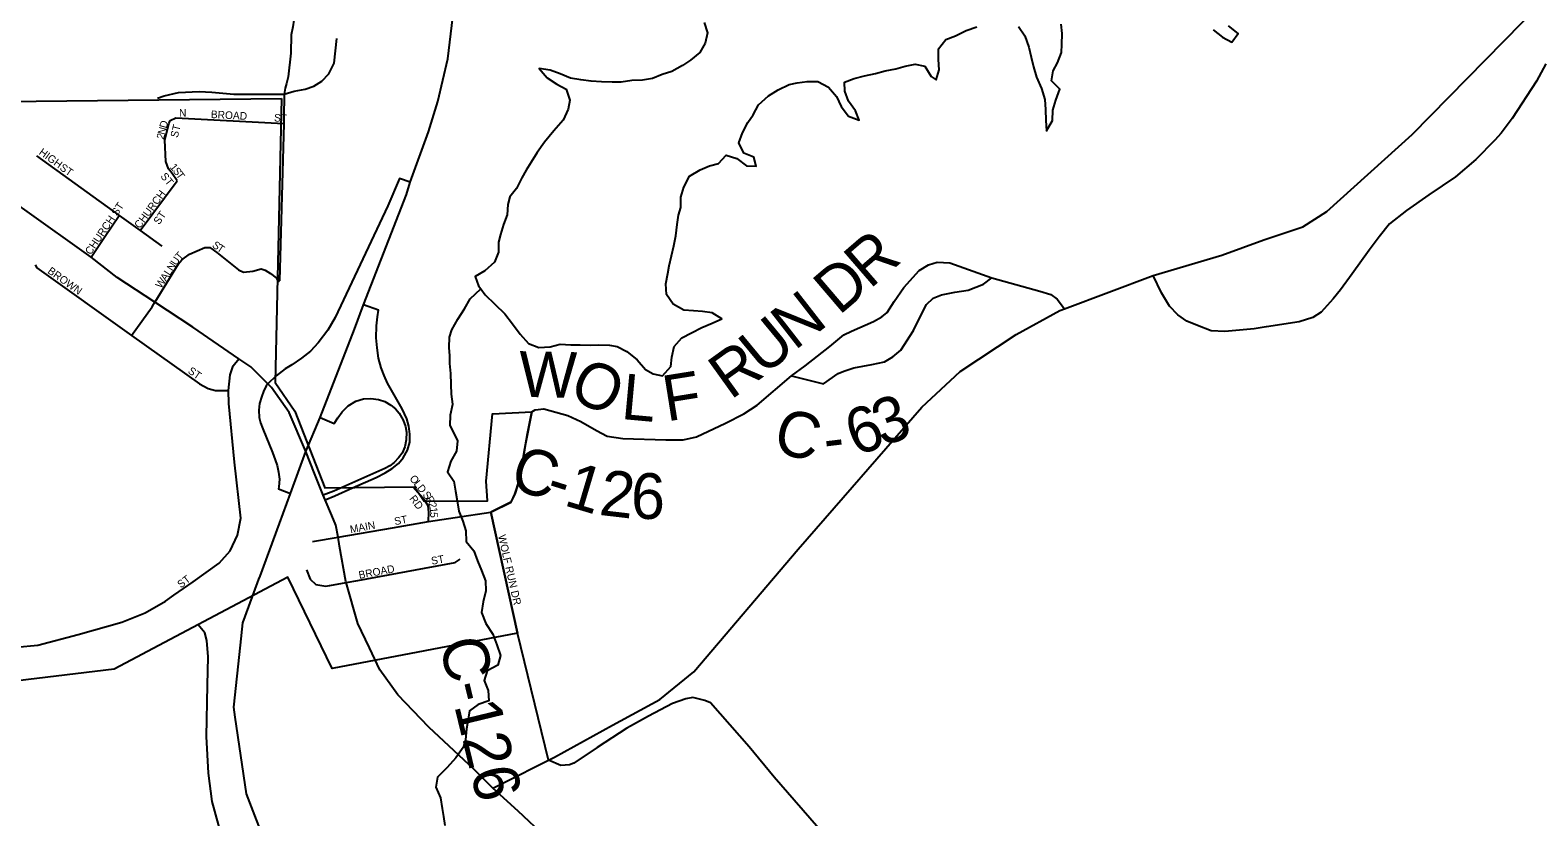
# Model space of a CAD drawing. Extents: x -22 to 431, y -18 to 160.
# Drawn here: x 323.412 to 325.283, y 148.89 to 149.867 of the extents above; entities that cross this region are included whole.
import ezdxf

# ---------------------------------------------------------------- set-up
doc = ezdxf.new("R2010")
doc.units = 0
for name, color, linetype in [('GM_X_Adjacent_County_Text', 7, 'Continuous'), ('GM_X_City_Street', 7, 'Continuous'), ('GM_X_Corporation_Text', 7, 'Continuous'), ('GM_X_County_ROW', 7, 'Continuous'), ('GM_X_County_Subdivision_Text', 7, 'Continuous'), ('GM_X_Minor_River_Text', 7, 'Continuous'), ('GM_X_Rail_Line', 7, 'Continuous'), ('GM_X_Section_Text', 7, 'Continuous'), ('GM_X_State_Route', 7, 'Continuous'), ('GM_X_Township_Subdivision', 7, 'Continuous'), ('GM_X_Township_Subdivision_Text', 7, 'Continuous')]:
    doc.layers.add(name, color=color, linetype=linetype)

msp = doc.modelspace()

# ---------------------------------------------------------------- linework, layer by layer
at = {"layer": 'GM_X_Adjacent_County_Text'}
for points in [[(324.3569, 149.4379), (324.3569, 149.4379), (324.3735, 149.4501), (324.4045, 149.474), (324.4219, 149.4885), (324.4314, 149.4934), (324.4587, 149.5052), (324.4689, 149.5109), (324.4753, 149.5166), (324.484, 149.5303), (324.4961, 149.5477), (324.5154, 149.5686), (324.5268, 149.5758), (324.5374, 149.5789), (324.5533, 149.5782), (324.6054, 149.5594)], [(324.3569, 149.4379), (324.3966, 149.4277), (324.4148, 149.4407), (324.4216, 149.4437), (324.4341, 149.4479), (324.4564, 149.4517), (324.472, 149.4552), (324.4826, 149.4612), (324.4924, 149.4697), (324.5083, 149.4939), (324.5219, 149.522), (324.5245, 149.5265), (324.5325, 149.5341), (324.5431, 149.5383), (324.5594, 149.5418), (324.576, 149.5441), (324.5949, 149.5517), (324.6054, 149.5594)], [(324.6054, 149.5594), (324.665, 149.543), (324.6786, 149.5389), (324.6866, 149.5328), (324.6954, 149.521)], [(324.0343, 149.3931), (324.0343, 149.3931), (324.0384, 149.3954), (324.0494, 149.3969), (324.0793, 149.3886), (324.0952, 149.381), (324.1146, 149.3697), (324.1278, 149.3629), (324.1475, 149.3599), (324.2009, 149.3581), (324.2221, 149.3581), (324.2388, 149.3619), (324.2747, 149.379), (324.2974, 149.3904), (324.3141, 149.4015), (324.3569, 149.4379)], [(324.0551, 148.9604), (324.0166, 149.1182)], [(324.396, 148.8691), (324.3353, 148.9392), (324.3042, 148.9767), (324.2561, 149.0316), (324.2493, 149.0346), (324.2341, 149.038), (324.2254, 149.0365), (324.2091, 149.0308), (324.1792, 149.0148), (324.1571, 149.0026)], [(324.1571, 149.0026), (324.1567, 149.0024), (324.1524, 149), (324.1156, 148.976), (324.0865, 148.9566), (324.0812, 148.9544), (324.0706, 148.9536), (324.0551, 148.9604)]]:
    msp.add_lwpolyline(points, dxfattribs=at)
at = {"layer": 'GM_X_County_ROW'}
for points in [[(323.9862, 148.9254), (323.9991, 148.9322), (324.0551, 148.9604), (324.0626, 148.9642), (324.1346, 149.0037), (324.1932, 149.0357), (324.2356, 149.0699), (324.3652, 149.2224), (324.5186, 149.3989), (324.5663, 149.4432), (324.6355, 149.4891), (324.69, 149.5189), (324.6954, 149.521), (324.8058, 149.5625), (324.8909, 149.5875), (324.9432, 149.6067), (324.9913, 149.6229), (325.0212, 149.642), (325.1271, 149.7375), (325.2643, 149.8771), (325.4249, 150.0397)], [(323.6708, 149.4589), (323.6136, 149.4982), (323.5665, 149.5292), (323.5196, 149.56), (323.4874, 149.5853), (323.4053, 149.644), (323.398, 149.6488)], [(323.7648, 149.3166), (323.7541, 149.3438), (323.7332, 149.3923), (323.7112, 149.4233), (323.7069, 149.4277), (323.6984, 149.4361), (323.6855, 149.4488), (323.6708, 149.4589)], [(323.7958, 149.226), (323.7939, 149.2374), (323.7913, 149.2524), (323.7862, 149.2644), (323.7779, 149.2839), (323.7756, 149.2895), (323.7648, 149.3166)], [(323.8329, 149.0997), (323.8232, 149.1206), (323.8186, 149.1303), (323.8038, 149.1809), (323.8034, 149.1821), (323.7958, 149.226)], [(323.9862, 148.9254), (323.9627, 148.9489), (323.9066, 149.0015), (323.8679, 149.0413), (323.8456, 149.0727), (323.8329, 149.0997)], [(324.3568, 148.2215), (324.3548, 148.2346), (324.3377, 148.3191), (324.3221, 148.3825), (324.2979, 148.4291), (324.2767, 148.4535), (324.2271, 148.5231), (324.1871, 148.5703), (324.1592, 148.6143), (324.1333, 148.6627), (324.1231, 148.6939), (324.1142, 148.7241), (324.1109, 148.7352), (324.1033, 148.7682), (324.0965, 148.7845), (324.0718, 148.8338), (324.0517, 148.8648), (324.0173, 148.897), (323.9862, 148.9254)]]:
    msp.add_lwpolyline(points, dxfattribs=at)
at = {"layer": 'GM_X_County_Subdivision_Text'}
msp.add_lwpolyline([(323.7239, 149.7823), (323.7157, 149.4296), (323.7403, 149.3939), (323.7774, 149.2986), (323.8886, 149.2997), (323.9008, 149.282), (323.9793, 149.2826), (323.9779, 149.3069), (323.9858, 149.3904), (324.0343, 149.3931), (324.0262, 149.3511), (324.0202, 149.3127), (324.0133, 149.2907), (324.0085, 149.2807), (323.9836, 149.2684), (324.0166, 149.1182), (323.7864, 149.074), (323.7314, 149.1875), (323.5161, 149.0733), (323.3959, 149.0588), (323.3327, 149.089), (323.2169, 149.0915), (323.2286, 149.7771)], close=True, dxfattribs=at)
at = {"layer": 'GM_X_Minor_River_Text'}
for points in [[(323.7392, 149.8797), (323.7377, 149.8713), (323.7358, 149.8615), (323.7351, 149.8387), (323.7321, 149.8091), (323.7298, 149.8008), (323.7284, 149.7951), (323.7272, 149.7875), (323.7268, 149.7583), (323.7266, 149.7514), (323.7213, 149.5557)], [(323.7272, 149.7875), (323.7395, 149.7914), (323.7531, 149.7938), (323.7637, 149.7976), (323.7738, 149.8038), (323.7825, 149.813), (323.7892, 149.8263), (323.7924, 149.8567)], [(325.2932, 149.8252), (325.2816, 149.8039), (325.2512, 149.7573), (325.2377, 149.7394), (325.2298, 149.7306), (325.2062, 149.7065), (325.181, 149.6851), (325.1478, 149.6628), (325.1203, 149.6433), (325.0992, 149.6264), (325.0861, 149.6104), (325.0737, 149.594), (325.0527, 149.5646), (325.0381, 149.5448), (325.0291, 149.5333), (325.014, 149.5169), (325.0039, 149.5104), (324.9869, 149.5049), (324.9464, 149.4986)], [(323.5697, 149.7827), (323.578, 149.7854), (323.5958, 149.7896), (323.6215, 149.7911), (323.6371, 149.79), (323.6647, 149.7878), (323.7272, 149.7875)], [(324.9464, 149.4986), (324.9461, 149.4985), (324.9309, 149.4962), (324.8946, 149.4928), (324.8775, 149.4935), (324.8608, 149.5002), (324.8475, 149.5057), (324.8361, 149.5136), (324.8258, 149.5242), (324.8162, 149.5408), (324.8058, 149.5625)], [(323.856, 148.5271), (323.856, 148.5274), (323.8375, 148.5686), (323.8264, 148.5894), (323.8118, 148.6139), (323.7908, 148.6429), (323.7614, 148.6806), (323.7071, 148.7477), (323.696, 148.7639), (323.6792, 148.7957), (323.6499, 148.8637), (323.6378, 148.9088), (323.633, 148.944), (323.6305, 148.9899), (323.6319, 149.0536), (323.6328, 149.0885), (323.6311, 149.109), (323.6284, 149.1184), (323.6204, 149.1286)]]:
    msp.add_lwpolyline(points, dxfattribs=at)
at = {"layer": 'GM_X_Rail_Line'}
for points in [[(323.7541, 149.3438), (323.7718, 149.3859), (323.8142, 149.4956), (323.8253, 149.5261), (323.8788, 149.6629), (323.8836, 149.6785), (323.906, 149.7408), (323.9176, 149.7784), (323.9303, 149.8316), (323.9399, 149.9149), (323.9389, 150.0683), (323.9274, 150.2851), (323.911, 150.5141), (323.8962, 150.7806), (323.8747, 151.1376), (323.8507, 151.5599)], [(323.7445, 149.3178), (323.7541, 149.3438)], [(323.7212, 149.2544), (323.735, 149.2918), (323.7445, 149.3178)], [(323.6971, 149.1888), (323.7212, 149.2544)], [(323.6833, 149.1514), (323.6957, 149.1851), (323.6971, 149.1888)], [(323.6727, 149.103), (323.6757, 149.1309), (323.6833, 149.1514)], [(323.6662, 149.0139), (323.6644, 149.0261), (323.6727, 149.103)], [(324.2676, 147.6799), (324.2465, 147.7384), (324.2135, 147.824), (324.1675, 147.9385), (324.1073, 148.0954), (324.0457, 148.2492), (324.0077, 148.347), (323.9615, 148.4417), (323.9126, 148.5147), (323.8297, 148.6521), (323.766, 148.738), (323.706, 148.852), (323.6803, 148.9187), (323.6662, 149.0139)]]:
    msp.add_lwpolyline(points, dxfattribs=at)
at = {"layer": 'GM_X_Section_Text'}
for points in [[(323.5835, 149.6949), (323.5803, 149.7039), (323.5789, 149.7305), (323.5839, 149.751), (323.5857, 149.7548)], [(323.5857, 149.7548), (323.5925, 149.7583), (323.7266, 149.7514)], [(323.4198, 149.7109), (323.5224, 149.6369), (323.5484, 149.6182), (323.5753, 149.5988)], [(323.5484, 149.6182), (323.5943, 149.6799)], [(323.5943, 149.6799), (323.5881, 149.6893), (323.5835, 149.6949)], [(323.5049, 149.6111), (323.5224, 149.6369)], [(323.4874, 149.5853), (323.5049, 149.6111), (323.5049, 149.6111)], [(323.5668, 149.5297), (323.596, 149.5767), (323.6001, 149.5817), (323.6094, 149.5887), (323.6286, 149.5973), (323.6347, 149.5973), (323.6359, 149.5965)], [(323.6359, 149.5965), (323.636, 149.5964), (323.6435, 149.591), (323.6703, 149.5694), (323.6764, 149.5664), (323.6881, 149.5677), (323.6986, 149.5705), (323.7036, 149.5691), (323.7101, 149.565), (323.7169, 149.5594), (323.7193, 149.5553), (323.7205, 149.555), (323.7213, 149.5557)], [(323.4181, 149.5755), (323.42, 149.5721), (323.5376, 149.4878), (323.6221, 149.4277), (323.6328, 149.4221), (323.6419, 149.4196), (323.6579, 149.4194)], [(323.5376, 149.4878), (323.563, 149.5236), (323.5665, 149.5292), (323.5666, 149.5294), (323.5668, 149.5297)], [(323.3945, 149.1005), (323.4214, 149.1032), (323.4714, 149.1165), (323.5255, 149.1318), (323.5543, 149.1432), (323.5797, 149.1577), (323.5899, 149.1653), (323.6141, 149.182), (323.6463, 149.2052), (323.6599, 149.2204), (323.669, 149.2397), (323.6731, 149.261), (323.6655, 149.3304), (323.6582, 149.4035), (323.6579, 149.4194), (323.6601, 149.4392), (323.6639, 149.4502), (323.6708, 149.4589)], [(323.9836, 149.2684), (324.0086, 149.2809), (324.0134, 149.2908), (324.0154, 149.2971), (324.0203, 149.3132), (324.0246, 149.3405), (324.0291, 149.3663), (324.0343, 149.3931)], [(323.9063, 149.2567), (323.9065, 149.2684), (323.9057, 149.2763), (323.9018, 149.2827), (323.8876, 149.2992)], [(323.9392, 149.2617), (323.9836, 149.2684)], [(324.0166, 149.1182), (323.9836, 149.2684)], [(323.762, 149.232), (323.7939, 149.2374), (323.8616, 149.2491)], [(323.8616, 149.2491), (323.9063, 149.2567), (323.9392, 149.2617)], [(323.7833, 149.1773), (323.7835, 149.1773), (323.8038, 149.1809), (323.8183, 149.1834), (323.9391, 149.2059), (323.9455, 149.2101)], [(323.7549, 149.1966), (323.7592, 149.1853), (323.7665, 149.1786), (323.7786, 149.1764), (323.7833, 149.1773)]]:
    msp.add_lwpolyline(points, dxfattribs=at)
at = {"layer": 'GM_X_State_Route'}
for points in [[(323.8836, 149.6785), (323.87, 149.6827), (323.8555, 149.6488), (323.7904, 149.5102), (323.7811, 149.4943), (323.7694, 149.4788), (323.7597, 149.4682), (323.7486, 149.4597), (323.7367, 149.4514), (323.7281, 149.4466), (323.717, 149.4379), (323.7069, 149.4277)], [(323.7779, 149.2839), (323.7898, 149.2889), (323.8117, 149.2988), (323.8414, 149.3116), (323.8523, 149.3171), (323.8612, 149.3226), (323.8691, 149.329), (323.8747, 149.336), (323.8799, 149.3453), (323.8829, 149.3555), (323.8829, 149.3653), (323.8819, 149.3752), (323.8793, 149.3842), (323.8733, 149.3966), (323.8554, 149.4288), (323.8511, 149.4382), (323.8474, 149.4479), (323.8443, 149.4597), (323.8424, 149.4725), (323.8412, 149.4851), (323.8415, 149.4997), (323.8429, 149.511), (323.8443, 149.5192), (323.8253, 149.5261)], [(323.7069, 149.4277), (323.7045, 149.4253), (323.7014, 149.4184), (323.6992, 149.4123), (323.6965, 149.4034), (323.6954, 149.3953), (323.6959, 149.3861), (323.6976, 149.3793), (323.7004, 149.3718), (323.7126, 149.3424), (323.7159, 149.3336), (323.7183, 149.3265), (323.7201, 149.3181), (323.7211, 149.3093), (323.7205, 149.2997), (323.7199, 149.2974), (323.735, 149.2918)], [(323.7718, 149.3859), (323.7891, 149.3787), (323.7935, 149.3857), (323.7991, 149.393), (323.8064, 149.4004), (323.8159, 149.4062), (323.8253, 149.4092), (323.8345, 149.4097), (323.8441, 149.4085), (323.852, 149.4057), (323.8596, 149.4014), (323.8653, 149.3969), (323.8698, 149.3912), (323.8749, 149.3828), (323.8775, 149.375), (323.8787, 149.3676), (323.8786, 149.3582), (323.8766, 149.3497), (323.8734, 149.3417), (323.869, 149.3357), (323.8635, 149.3301), (323.858, 149.3261), (323.8518, 149.3226), (323.7885, 149.2945), (323.7756, 149.2895)]]:
    msp.add_lwpolyline(points, dxfattribs=at)
at = {"layer": 'GM_X_Township_Subdivision'}
for points in [[(324.2483, 149.8765), (324.2526, 149.8637), (324.2497, 149.8512), (324.243, 149.8393), (324.2313, 149.8297), (324.2215, 149.8232), (324.208, 149.8158), (324.1963, 149.8119), (324.1842, 149.8072), (324.1717, 149.8052), (324.1585, 149.8047), (324.1453, 149.8026), (324.1343, 149.8025), (324.121, 149.8031), (324.1081, 149.8037), (324.0952, 149.8055), (324.0823, 149.8076), (324.0694, 149.8128), (324.0573, 149.8176), (324.0436, 149.8197), (324.0536, 149.8081), (324.0654, 149.8002), (324.0772, 149.7939), (324.0815, 149.7803), (324.0797, 149.7689), (324.0734, 149.7552), (324.0618, 149.7422), (324.0502, 149.728), (324.0409, 149.7154), (324.0338, 149.7032), (324.0275, 149.6933), (324.0219, 149.6837), (324.0152, 149.6704), (324.007, 149.6601), (324.0048, 149.6506), (324.0038, 149.6377), (323.9994, 149.6259), (323.9954, 149.6133), (323.9932, 149.6038), (323.9929, 149.5913), (323.9881, 149.5791), (323.9761, 149.568), (323.9641, 149.561), (323.9684, 149.5497), (323.9711, 149.5458)], [(324.5299, 149.8095), (324.5364, 149.8054), (324.5401, 149.8179), (324.5392, 149.8308), (324.539, 149.8441), (324.5484, 149.8555), (324.5604, 149.8602), (324.5736, 149.8668), (324.5868, 149.8711)], [(324.6383, 149.8717), (324.6464, 149.86), (324.6515, 149.846), (324.6543, 149.8336), (324.657, 149.8218), (324.6609, 149.8086), (324.6671, 149.7946), (324.6711, 149.781), (324.672, 149.7685), (324.6725, 149.7549), (324.6734, 149.742), (324.6808, 149.755), (324.6811, 149.7679), (324.6847, 149.78), (324.6899, 149.7937), (324.6795, 149.8043), (324.6817, 149.8168), (324.6869, 149.8267), (324.6917, 149.8396), (324.6923, 149.8495), (324.6929, 149.8632), (324.6913, 149.8745)], [(324.88, 149.8675), (324.8918, 149.8585), (324.9032, 149.8522), (324.9111, 149.8629), (324.8992, 149.8726)], [(324.2098, 149.5269), (324.2014, 149.5386), (324.2008, 149.5522), (324.2034, 149.5648), (324.2048, 149.5743), (324.2106, 149.5994), (324.2131, 149.6115), (324.2149, 149.6256), (324.2166, 149.6373), (324.2192, 149.6468), (324.2194, 149.6597), (324.2231, 149.6723), (324.2301, 149.6856), (324.2433, 149.6937), (324.255, 149.6988), (324.266, 149.7016), (324.2757, 149.7119), (324.289, 149.7079), (324.3008, 149.6985), (324.3129, 149.6983), (324.3098, 149.7092), (324.2976, 149.7144), (324.2914, 149.7272), (324.2959, 149.7398), (324.3025, 149.7524), (324.3093, 149.7619), (324.3159, 149.7745), (324.328, 149.7856), (324.34, 149.793), (324.3539, 149.7996), (324.3638, 149.8016), (324.3762, 149.8036), (324.3895, 149.8034), (324.4028, 149.7963), (324.4124, 149.7847), (324.4182, 149.7722), (324.4274, 149.7602), (324.4407, 149.7554), (324.4361, 149.7671), (324.4276, 149.7791), (324.4229, 149.7912), (324.4224, 149.8026), (324.4345, 149.8073), (324.4474, 149.8105), (324.461, 149.8133), (324.473, 149.8168), (324.4863, 149.8192), (324.498, 149.8224), (324.5104, 149.8248), (324.5222, 149.8223), (324.5299, 149.8095)], [(323.9711, 149.5458), (323.9764, 149.5384), (323.9887, 149.5268), (324.0009, 149.5148), (324.0105, 149.5024), (324.0201, 149.4896), (324.0304, 149.478), (324.043, 149.4728), (324.057, 149.4737), (324.0695, 149.4773), (324.0827, 149.4763), (324.0945, 149.4764), (324.107, 149.4758), (324.1172, 149.4763), (324.1308, 149.4757), (324.1403, 149.4742), (324.1525, 149.4679), (324.1651, 149.4578), (324.1754, 149.4458), (324.185, 149.4402), (324.1967, 149.4377), (324.2068, 149.4492), (324.2082, 149.4609), (324.2111, 149.4742), (324.2208, 149.485), (324.2325, 149.4912), (324.2453, 149.4977), (324.2581, 149.5032), (324.2702, 149.5086), (324.2584, 149.5161), (324.2463, 149.5175), (324.2349, 149.5185), (324.2231, 149.5195), (324.2098, 149.5269)]]:
    msp.add_lwpolyline(points, dxfattribs=at)
at = {"layer": 'GM_X_Township_Subdivision_Text'}
for points in [[(323.9331, 149.3758), (323.933, 149.3757), (323.9333, 149.3893), (323.9362, 149.4026), (323.9349, 149.4148), (323.9344, 149.4269), (323.9339, 149.4405), (323.9326, 149.453), (323.9325, 149.4625), (323.9317, 149.4731), (323.9323, 149.4856), (323.9352, 149.4951), (323.9427, 149.5081), (323.9509, 149.5211), (323.9579, 149.5333), (323.9711, 149.5458)], [(323.9331, 149.3758), (323.9423, 149.3572), (323.9409, 149.3443), (323.9339, 149.3317), (323.9298, 149.3184), (323.9375, 149.3071), (323.9396, 149.2946), (323.9419, 149.2825), (323.944, 149.2697), (323.9486, 149.2572), (323.9526, 149.2451), (323.9531, 149.2318), (323.9623, 149.2202), (323.9669, 149.2081), (323.972, 149.196), (323.977, 149.1832), (323.9772, 149.1707), (323.9739, 149.157), (323.9721, 149.1437), (323.9772, 149.1301), (323.9861, 149.117), (323.9911, 149.1034), (323.9954, 149.0905), (323.9921, 149.0784), (323.9789, 149.0714), (323.9753, 149.0592), (323.9803, 149.0468), (323.9812, 149.0339), (323.968, 149.0296), (323.9571, 149.0215), (323.955, 149.0086), (323.9532, 148.9991), (323.9522, 148.9854), (323.9493, 148.9759), (323.9403, 148.9633), (323.9294, 148.9511), (323.9174, 148.9392), (323.9153, 148.927), (323.9211, 148.9134), (323.9231, 148.9002), (323.9248, 148.8903), (323.9264, 148.879)]]:
    msp.add_lwpolyline(points, dxfattribs=at)

# ---------------------------------------------------------------- texts
at = {"layer": 'GM_X_City_Street'}
for s, height, rotation, p in [('R', 0.0568, 40.8254, (324.4539, 149.5447)), ('D', 0.0568, 40.4787, (324.4156, 149.512)), ('N', 0.0568, 37.9088, (324.3605, 149.4684)), ('U', 0.0568, 39.5671, (324.3223, 149.4368)), ('R', 0.0568, 35.6808, (324.2811, 149.4071)), ('W', 0.0568, 358.8739, (324.0182, 149.4117)), ('O', 0.0568, 334.3277, (324.0778, 149.4118)), ('L', 0.0568, 354.7876, (324.1441, 149.3843)), ('F', 0.0568, 9.0926, (324.2019, 149.381)), ('6', 0.0568, 20.1964, (324.4366, 149.3374)), ('3', 0.0568, 20.3601, (324.4697, 149.3495)), ('C', 0.0568, 346.1465, (324.3319, 149.3438)), ('-', 0.0568, 6.9111, (324.3995, 149.3312)), ('C', 0.0568, 342.2019, (324.0047, 149.2991)), ('1', 0.0568, 343.3517, (324.0726, 149.2774)), ('-', 0.0568, 342.3963, (324.0493, 149.2847)), ('2', 0.0568, 353.3579, (324.1167, 149.2652)), ('6', 0.0568, 358.2651, (324.1568, 149.2607)), ('C-126', 0.05682, 283.6351, (323.919, 149.1064))]:
    msp.add_text(s, height=height, rotation=rotation, dxfattribs=at).set_placement(p)
at = {"layer": 'GM_X_Corporation_Text'}
for s, rotation, p in [('D', 74.0816, (323.5809, 149.7446)), ('N', 0, (323.5966, 149.7597)), ('BROAD', 357.0909, (323.6358, 149.758)), ('ST', 356.1879, (323.7142, 149.7539)), ('2', 75.9335, (323.5775, 149.7309)), ('N', 75.916, (323.5789, 149.7366)), ('ST', 75.9573, (323.5948, 149.7329)), ('HIGH', 324.0898, (323.4217, 149.7136)), ('ST', 325.3092, (323.4475, 149.6944)), ('1', 309.8056, (323.5845, 149.6967)), ('S', 307.7168, (323.5882, 149.6922)), ('ST', 309.0829, (323.5729, 149.6855)), ('T', 306.411, (323.5922, 149.687)), ('CHURCH', 53.3211, (323.5477, 149.6199)), ('CHURCH ST', 55.904, (323.4869, 149.5873)), ('ST', 55.2978, (323.5718, 149.6248)), ('S', 322.7312, (323.6368, 149.5985)), ('T', 326.094, (323.6426, 149.5941)), ('U', 56.5766, (323.5932, 149.5741)), ('T', 46.3331, (323.5975, 149.5807)), ('BROWN', 324.4633, (323.4325, 149.5661)), ('L', 56.5752, (323.5849, 149.5616)), ('N', 56.5811, (323.5886, 149.5671)), ('W', 56.5757, (323.5743, 149.5456)), ('A', 56.5811, (323.5803, 149.5546)), ('ST', 325.3092, (323.6067, 149.4419)), ('O', 308.7281, (323.882, 149.3099)), ('L', 308.7013, (323.8872, 149.3034)), ('D', 308.7219, (323.8914, 149.2982)), ('RD', 307.4135, (323.8819, 149.2851)), ('S', 308.7281, (323.8982, 149.2898)), ('R', 302.4507, (323.9022, 149.2848)), ('2', 287.6353, (323.906, 149.279)), ('1', 275.4403, (323.9076, 149.274)), ('5', 270.5932, (323.9082, 149.2684)), ('MAIN', 10.7134, (323.8096, 149.2422)), ('ST', 10.6147, (323.8646, 149.2522)), ('WOLF RUN DR', 282.8582, (323.9924, 149.2392)), ('ST', 10.6279, (323.9104, 149.203)), ('ST', 37.5735, (323.5989, 149.1735)), ('BROAD', 10.6227, (323.8204, 149.1855))]:
    msp.add_text(s, height=0.00947, rotation=rotation, dxfattribs=at).set_placement(p)

doc.saveas('drawing.dxf')
